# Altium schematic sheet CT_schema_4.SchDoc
size 300 x 182 mm
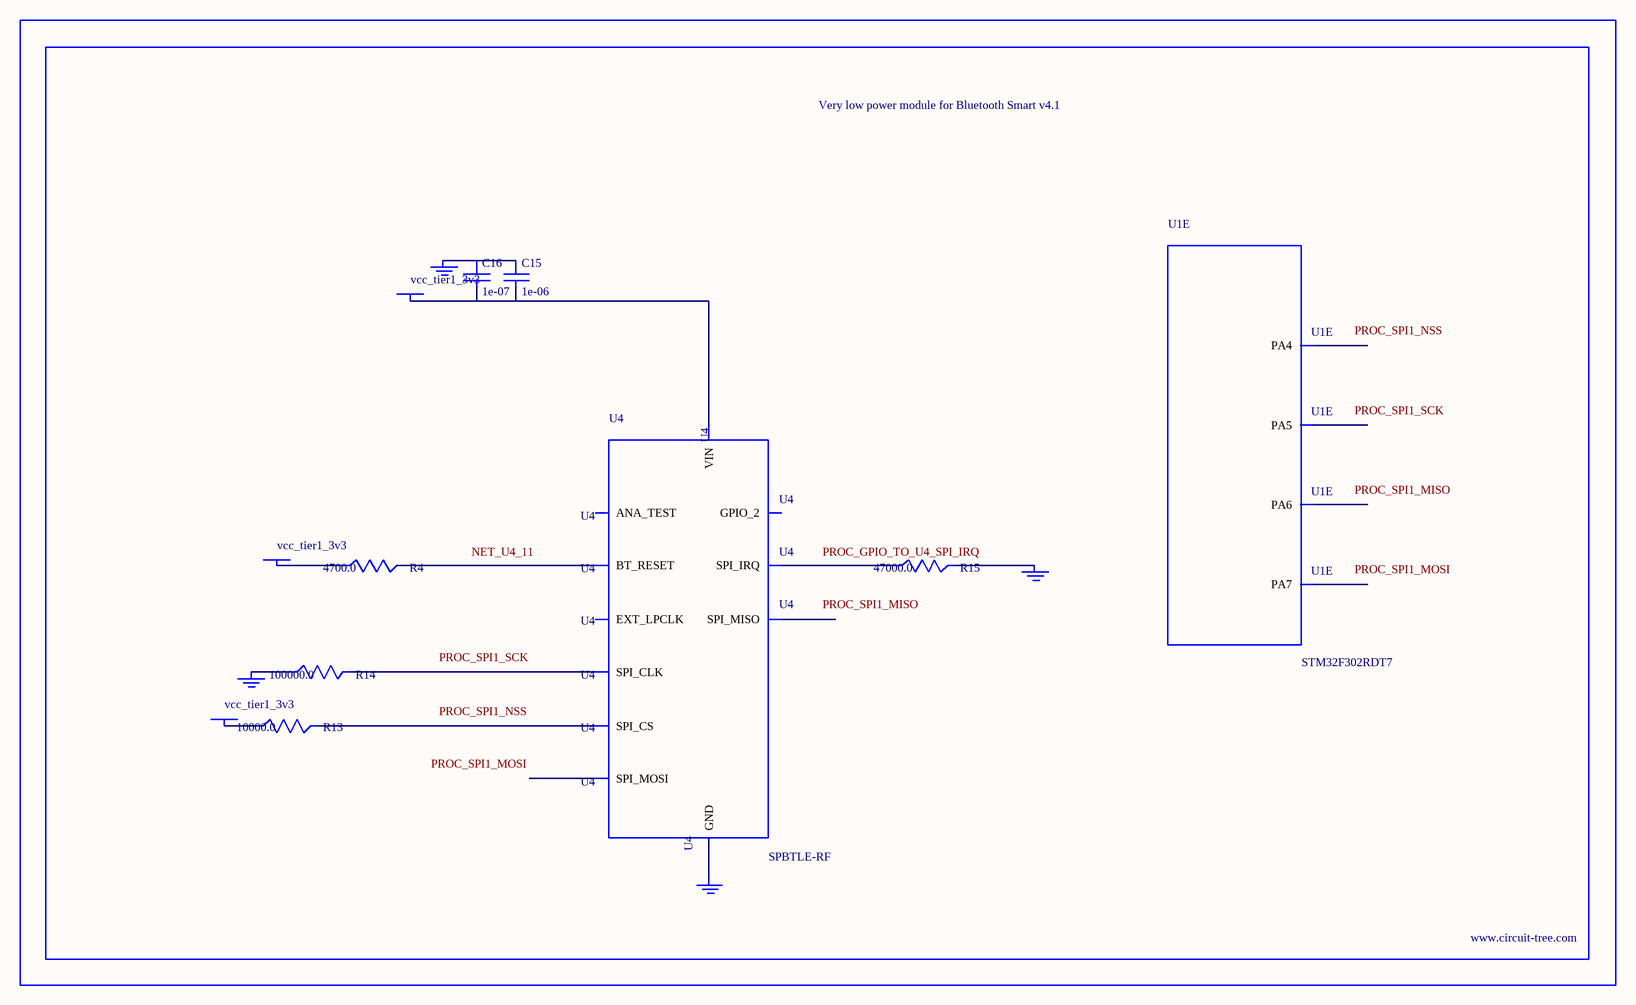
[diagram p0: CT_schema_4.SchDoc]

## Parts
BORDER3  (no value)
C15  1e-06  [C0603]
C16  1e-07  [C0402]
GND_INSTANCE_3_0  (no value)
GND_INSTANCE_3_1  (no value)
GND_INSTANCE_3_2  (no value)
GND_INSTANCE_3_3  (no value)
POWER_INSTANCE_3_0  vcc_tier1_3v3
POWER_INSTANCE_3_1  vcc_tier1_3v3
POWER_INSTANCE_3_2  vcc_tier1_3v3
R4  4700.0  [R0603]
R13  10000.0  [R0603]
R14  100000.0  [R0603]
R15  47000.0  [R0603]
U1  STM32F302RDT7  [LQFP64]  (part E of 7)
U4  SPBTLE-RF  [XCVR_SPBTLE-RF]

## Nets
NetC15_1: C15.1 C16.1 GND_INSTANCE_3_1.0(GND)
NetC15_2: C15.2 C16.2 POWER_INSTANCE_3_0.0(PWR) U4.5(VIN)
NetGND_INSTANCE_3_0_0: GND_INSTANCE_3_0.0(GND) R15.2
NetGND_INSTANCE_3_2_0: GND_INSTANCE_3_2.0(GND) R14.1
NetGND_INSTANCE_3_3_0: GND_INSTANCE_3_3.0(GND) U4.6(GND)
NetPOWER_INSTANCE_3_1_0: POWER_INSTANCE_3_1.0(PWR) R13.1
NetPOWER_INSTANCE_3_2_0: POWER_INSTANCE_3_2.0(PWR) R4.1
NetR4_2: R4.2 U4.11(BT_RESET)
NetR13_2: R13.2 U4.10(SPI_CS)
NetR14_2: R14.2 U4.7(SPI_CLK)
NetR15_1: R15.1 U4.4(SPI_IRQ)

Not connected (* = marked no-connect by the designer): U1 20(PA4) 21(PA5) 22(PA6) 23(PA7); U4 1(EXT_LPCLK) 2(GPIO_2) 3(ANA_TEST) 8(SPI_MISO) 9(SPI_MOSI)

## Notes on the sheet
- Labels drawn without touching a wire or pin: NET_U4_11, PROC_GPIO_TO_U4_SPI_IRQ, PROC_SPI1_MISO, PROC_SPI1_MOSI, PROC_SPI1_NSS, PROC_SPI1_SCK

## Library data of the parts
BORDER3 = BORDER_PAGE3
C15 = C0603C105K3RACTU
C16 = C0402C104K3RACTU
GND_INSTANCE_3_0-GND_INSTANCE_3_3 = GND
POWER_INSTANCE_3_0-POWER_INSTANCE_3_2 = PWR
R4 = RC0603JR-074K7L
R13 = RC0603JR-0710KL
R14 = RC0603JR-07100KL
R15 = RC0603JR-0747KL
